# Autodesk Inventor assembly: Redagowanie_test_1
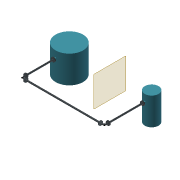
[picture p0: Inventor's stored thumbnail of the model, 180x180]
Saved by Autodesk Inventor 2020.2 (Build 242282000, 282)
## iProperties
Created: 2014-08
Part Number: Redagowanie_test_1
Document SubType Name: Assembly
Designer: F.Stasiak
Catalog Web Link: www.expertbooks.pl
Manager: www.cadconsulting.pl
Company: Fabian Stasiak CAD Consulting
Author: F.Stasiak
Subject: Zbiór ćwiczeń. Autodesk Inventor 2020. Kurs Professional
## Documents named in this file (4)
- C:\2020_Kurs_Professional\R1 Rury\Redagowanie_test_1.iam
- C:\2020_Kurs_Professional\R1 Rury\Konstrukcja_10.ipt
- C:\2020_Kurs_Professional\Zasoby\ContentCenter\pl-PL\ISO 7005-1 PN 40\ISO 7005-1 Kołnierz gwintowany z piastą, typ 13 - ISO PN 40 DN40 - 1 1_2.ipt
- C:\2020_Kurs_Professional\R1 Rury\Redagowanie_test_1\AIP\Przewody rurowe\Redagowanie_test_1.Przebiegi przewodów rurowych.iam
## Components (4 placed, 3 different names)
1. Konstrukcja_10:1 — Wstaw:1, Wstaw:2
2. ISO 7005-1 Kołnierz gwintowany z piastą, typ 13 - ISO PN 40 DN40 - 1 1/2:1 — Wstaw:1
3. ISO 7005-1 Kołnierz gwintowany z piastą, typ 13 - ISO PN 40 DN40 - 1 1/2:2 — Wstaw:2
4. Przebiegi przewodów rurowych [sub-assembly]
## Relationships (2: Insert 2)
- Wstaw:1 [Insert]: Konstrukcja_10:1 ↔ ISO 7005-1 Kołnierz gwintowany z piastą, typ 13 - ISO PN 40 DN40 - 1 1/2:1
- Wstaw:2 [Insert]: Konstrukcja_10:1 ↔ ISO 7005-1 Kołnierz gwintowany z piastą, typ 13 - ISO PN 40 DN40 - 1 1/2:2
